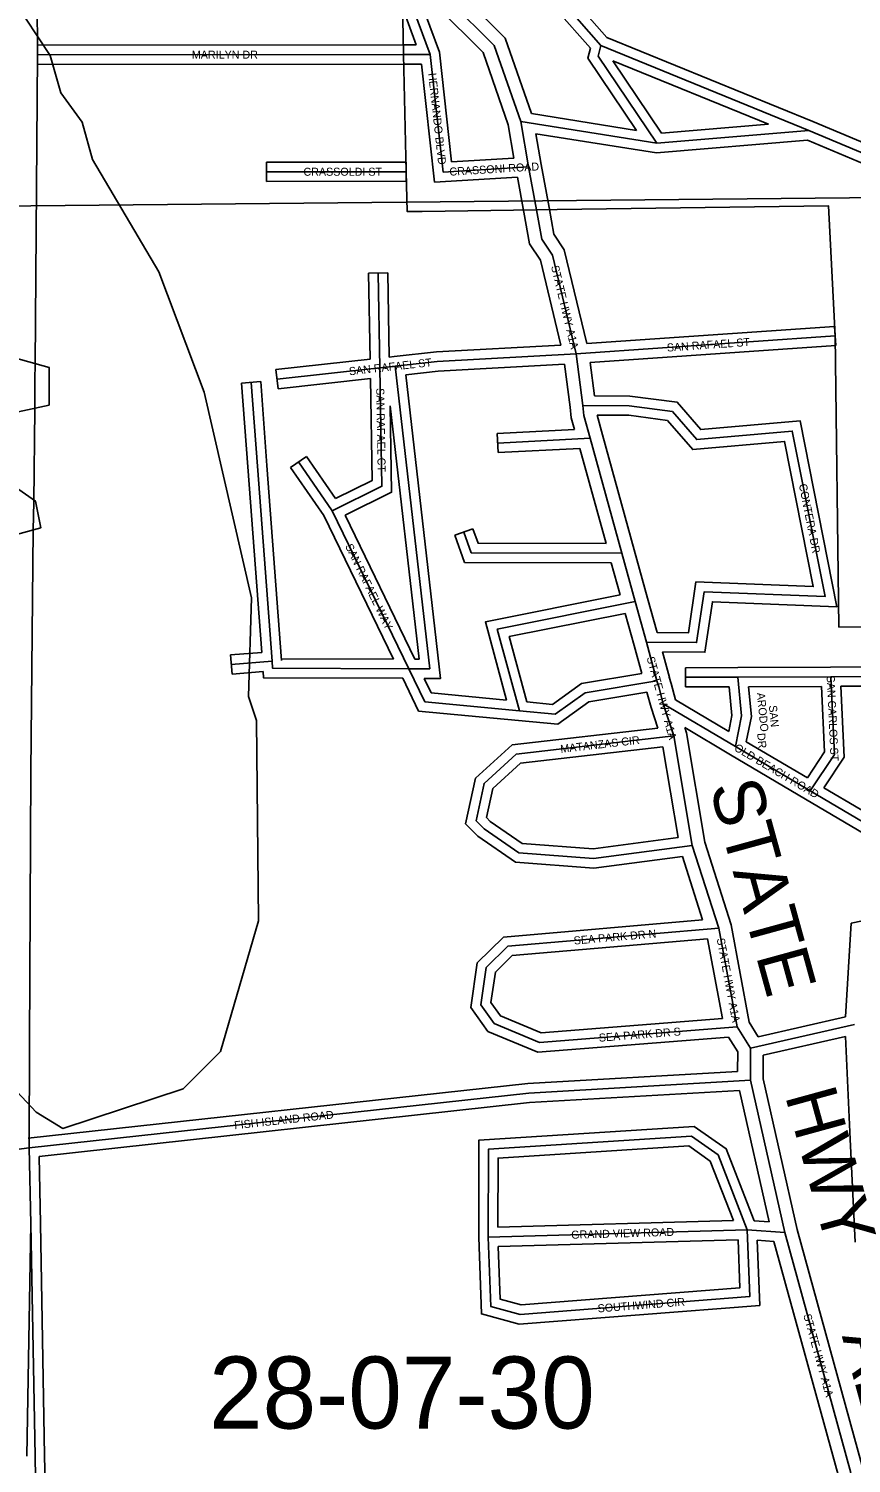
# Model space of a CAD drawing. Extents: x 418523 to 616617, y 1878279 to 2196743.
# Drawn here: x 564365 to 566933, y 2010108 to 2014588 of the extents above; entities that cross this region are included whole.
import ezdxf

# ---------------------------------------------------------------- set-up
doc = ezdxf.new("R2010")
doc.units = 0
for name, color, linetype in [('Level 1', 7, 'Continuous'), ('Level 2', 7, 'Continuous'), ('Level 22', 7, 'Continuous'), ('Level 23', 7, 'Continuous'), ('Level 28', 7, 'Continuous'), ('Level 31', 7, 'Continuous'), ('Level 32', 7, 'Continuous'), ('Level 34', 7, 'Continuous'), ('Level 5', 7, 'Continuous'), ('Level 7', 7, 'Continuous'), ('Level 8', 7, 'Continuous')]:
    doc.layers.add(name, color=color, linetype=linetype)

msp = doc.modelspace()

# ---------------------------------------------------------------- linework, layer by layer
at = {"layer": 'Level 1'}
msp.add_line((562889.28, 2014020.741), (568168.027, 2014072.298), dxfattribs=at)
at = {"layer": 'Level 22'}
for p, q in [((565925.146, 2014156.548), (565900.773, 2014298.436)), ((565949.857, 2014022.661), (565925.146, 2014156.548)), ((566094.474, 2013411.356), (566073.633, 2013572.508)), ((566216.957, 2012949.935), (566117.994, 2013309.11)), ((566258.427, 2012798.915), (566216.957, 2012949.935)), ((566293.299, 2012672.276), (566258.427, 2012798.915)), ((566326.287, 2012551.823), (566293.299, 2012672.276)), ((566331.628, 2012532.536), (566326.287, 2012551.823)), ((566346.079, 2012479.77), (566331.628, 2012532.536)), ((566379.116, 2012379.682), (566346.079, 2012479.77)), ((566436.603, 2012037.702), (566379.116, 2012379.682)), ((566519.019, 2011779.302), (566436.603, 2012037.702)), ((566576.589, 2011470.414), (566519.019, 2011779.302)), ((566618.267, 2011403.763), (566576.589, 2011470.414)), ((566618.023, 2011303.757), (566618.267, 2011403.763)), ((566724.954, 2010828.194), (566618.023, 2011303.757)), ((566931.388, 2010077.461), (566724.954, 2010828.194))]:
    msp.add_line(p, q, dxfattribs=at)
for points in [[(565900.773, 2014298.436), (565818, 2014536.473), (565679.829, 2014673.186)], [(566073.633, 2013572.508), (565999.589, 2013881.438), (565966.431, 2013931.341), (565949.857, 2014022.661)], [(566117.994, 2013309.11), (566098.202, 2013380.799), (566094.474, 2013411.356)]]:
    msp.add_lwpolyline(points, dxfattribs=at)
at = {"layer": 'Level 23'}
for p, q in [((565879.866, 2014183.873), (565861.908, 2014288.412)), ((565964.483, 2014163.807), (565947.874, 2014260.518)), ((565989.194, 2014029.92), (565964.483, 2014163.807)), ((565910.521, 2014015.401), (565890.404, 2014124.399)), ((566054.804, 2013406.225), (566037.44, 2013540.486)), ((566130.939, 2013441.266), (566117.463, 2013545.479)), ((566156.552, 2013319.755), (566139.576, 2013381.244)), ((566255.521, 2012960.56), (566156.558, 2013319.735)), ((566167.156, 2012980.096), (566085.247, 2013277.375)), ((566296.999, 2012809.506), (566255.53, 2012960.526)), ((566211.135, 2012820.076), (566183.685, 2012920.041)), ((566326.594, 2012702.04), (566296.992, 2012809.534)), ((566254.734, 2012661.656), (566227.083, 2012762.073)), ((566278.654, 2012574.316), (566254.719, 2012661.71)), ((566364.868, 2012562.388), (566343.087, 2012641.92)), ((566370.179, 2012543.211), (566364.838, 2012562.498)), ((566384.186, 2012492.068), (566370.209, 2012543.101)), ((566307.772, 2012468.21), (566294.643, 2012516.149)), ((566328.942, 2012404.073), (566307.772, 2012468.21)), ((566418.059, 2012389.321), (566412.746, 2012405.416)), ((566475.579, 2012047.141), (566418.059, 2012389.322)), ((566391.944, 2012062.076), (566344.309, 2012345.45)), ((566557.886, 2011789.081), (566475.579, 2012047.141)), ((566468.814, 2011805.074), (566405.574, 2012003.351)), ((566614.524, 2011485.194), (566557.886, 2011789.081)), ((566530.957, 2011496.933), (566484.498, 2011746.204)), ((566642.717, 2011440.107), (566614.524, 2011485.194)), ((566578.239, 2011392.331), (566549.553, 2011438.204)), ((566578.09, 2011331.512), (566578.239, 2011392.33)), ((566658.035, 2011308.151), (566658.215, 2011382.101)), ((566676.382, 2010861.878), (566584.217, 2011271.764)), ((566763.774, 2010837.889), (566658.035, 2011308.151)), ((566965.801, 2010103.183), (566763.775, 2010837.889)), ((566891.622, 2010071.21), (566691.049, 2010800.625))]:
    msp.add_line(p, q, dxfattribs=at)
for points in [[(565934.432, 2014323.433), (565852.733, 2014558.378), (565732.404, 2014677.438)], [(565861.909, 2014288.412), (565783.267, 2014514.568), (565639.966, 2014656.356)], [(566025.923, 2013599.948), (565962.344, 2013865.213), (565928.547, 2013916.078), (565910.499, 2014015.517)], [(566107.004, 2013604.899), (566036.834, 2013897.663), (566004.315, 2013946.604), (565989.215, 2014029.803)], [(566068.904, 2013336.612), (566058.854, 2013373.012), (566054.804, 2013406.225)]]:
    msp.add_lwpolyline(points, dxfattribs=at)
at = {"layer": 'Level 31'}
for p, q in [((565617.934, 2014507.874), (565556.854, 2014673.491)), ((566800.854, 2014270.771), (566151.431, 2014535.651)), ((565535.525, 2014507.715), (564392.277, 2014506.926)), ((565617.934, 2014507.874), (565535.525, 2014507.715)), ((565658.548, 2014140.478), (565617.934, 2014507.874)), ((566325.642, 2014230.476), (565900.773, 2014298.436)), ((566325.642, 2014230.476), (566800.854, 2014270.771)), ((567158.964, 2014120.071), (566800.854, 2014270.771)), ((565543.497, 2014141.853), (565106.731, 2014141.482)), ((565925.146, 2014156.548), (565658.548, 2014140.478)), ((565455.869, 2013825.322), (565461.157, 2013528.926)), ((566073.633, 2013572.508), (566882.65, 2013628.712)), ((565461.157, 2013528.926), (565139.989, 2013493.722)), ((565461.157, 2013528.926), (565509.349, 2013534.262)), ((565078.775, 2013221.856), (565059.139, 2013483.741)), ((566117.994, 2013309.11), (565829.205, 2013294.184)), ((565312.349, 2013082.722), (565207.178, 2013235.356)), ((565124.491, 2012612.613), (565078.775, 2013221.856)), ((565312.349, 2013082.722), (565551.464, 2012589.371)), ((565124.491, 2012612.613), (564997.361, 2012602.383)), ((565551.464, 2012589.371), (565601.789, 2012485.538)), ((566578.939, 2012563.205), (566415.064, 2012562.516)), ((566868.651, 2012564.315), (566578.939, 2012563.205)), ((567149.488, 2012565.451), (566868.651, 2012564.315)), ((565896.562, 2012457.601), (565601.789, 2012485.538)), ((566571.119, 2012346.483), (566346.079, 2012479.77)), ((566805.024, 2012208.085), (566571.119, 2012346.483)), ((566618.267, 2011403.763), (566943.35, 2011477.883)), ((564371.101, 2010855.837), (564366.621, 2011092.955)), ((566608.325, 2010836.842), (565799.644, 2010814.101)), ((566724.954, 2010828.194), (566608.325, 2010836.842))]:
    msp.add_line(p, q, dxfattribs=at)
for points in [[(566151.431, 2014535.651), (566031.009, 2014672.321), (566023.599, 2014676.651)], [(566325.642, 2014230.476), (566143.109, 2014502.216), (566151.431, 2014535.651)], [(565509.349, 2013534.262), (565640.289, 2013548.848), (566073.633, 2013572.508)], [(565461.157, 2013528.926), (565467.534, 2013159.069), (565312.349, 2013082.722)], [(565509.349, 2013534.262), (565617.003, 2012589.209), (565551.464, 2012589.371)], [(566094.474, 2013411.356), (566239.958, 2013410.998), (566374.305, 2013393.213), (566450.478, 2013305.021), (566748.804, 2013331.566), (566851.193, 2012814.556), (566473.722, 2012829.661), (566450.196, 2012671.163), (566293.299, 2012672.276)], [(566216.957, 2012949.935), (565746.584, 2012951.457), (565723.289, 2013016.246)], [(566258.427, 2012798.915), (565827.774, 2012713.06), (565896.562, 2012457.601)], [(565551.464, 2012589.371), (565126.022, 2012590.79), (565124.491, 2012612.613)], [(566578.939, 2012563.205), (566590.688, 2012442.077), (566571.119, 2012346.483)], [(566868.651, 2012564.315), (566880.104, 2012321.363), (566805.024, 2012208.085)], [(566326.287, 2012551.823), (566102.098, 2012514.553), (566008.427, 2012447.143), (565896.562, 2012457.601)], [(566436.603, 2012037.702), (566127.771, 2011997.003), (565894.52, 2012014.306), (565786.3, 2012089.486), (565761.322, 2012114.641), (565786.649, 2012231.312), (565887.038, 2012322.706), (566379.116, 2012379.682)], [(567236.134, 2011827.376), (567053.49, 2012061.288), (566805.024, 2012208.085)], [(565776.388, 2011539.294), (565793.475, 2011655.986), (565860.52, 2011722.371), (566519.019, 2011779.302)], [(566576.589, 2011470.414), (565959.629, 2011422.108), (565818.085, 2011481.006), (565776.388, 2011539.294)], [(564366.621, 2011092.955), (565925.959, 2011263.999), (566618.023, 2011303.757)], [(562952.402, 2010903.787), (564121.512, 2011060.113), (564366.621, 2011092.955)], [(566608.325, 2010836.842), (566517.288, 2011070.534), (566434.065, 2011129.287), (565800.32, 2011089.025), (565799.644, 2010814.101)], [(564388.429, 2009925.917), (564384.501, 2010130.303), (564371.101, 2010855.837)], [(565799.644, 2010814.101), (565807.352, 2010597.341), (565898.899, 2010572.022), (566616.059, 2010628.447), (566608.325, 2010836.842)]]:
    msp.add_lwpolyline(points, dxfattribs=at)
at = {"layer": 'Level 32'}
for p, q in [((565647.351, 2014514.814), (565587.229, 2014677.83)), ((566169.284, 2014560.77), (566067.283, 2014676.531)), ((565574.924, 2014537.791), (565526.601, 2014668.818)), ((565535.504, 2014537.715), (564392.257, 2014536.926)), ((564392.299, 2014476.926), (564392.257, 2014536.926)), ((565574.924, 2014537.79), (565535.467, 2014537.715)), ((566812.49, 2014298.422), (566169.284, 2014560.769)), ((565685.232, 2014172.141), (565647.351, 2014514.814)), ((565535.546, 2014477.714), (564392.299, 2014476.926)), ((565591.074, 2014477.821), (565535.584, 2014477.714)), ((565631.865, 2014108.813), (565591.073, 2014477.821)), ((566673.975, 2014290.121), (566188.789, 2014488.013)), ((566340.702, 2014261.861), (566188.789, 2014488.013)), ((566262.286, 2014270.991), (565934.432, 2014323.433)), ((566340.701, 2014261.861), (566673.975, 2014290.121)), ((567172.013, 2014147.128), (566812.49, 2014298.422)), ((566324.524, 2014200.272), (565947.874, 2014260.518)), ((566324.524, 2014200.272), (566796.029, 2014240.252)), ((567145.916, 2014093.011), (566796.029, 2014240.252)), ((565879.866, 2014183.872), (565685.232, 2014172.141)), ((565543.471, 2014171.853), (565106.706, 2014171.482)), ((565106.758, 2014111.481), (565106.706, 2014171.482)), ((565543.523, 2014111.852), (565543.471, 2014171.853)), ((565543.523, 2014111.852), (565106.758, 2014111.481)), ((565890.404, 2014124.398), (565631.865, 2014108.813)), ((565485.865, 2013825.857), (565425.873, 2013824.787)), ((565425.873, 2013824.787), (565430.674, 2013555.764)), ((565485.865, 2013825.857), (565490.567, 2013562.366)), ((566107.004, 2013604.899), (566880.572, 2013658.64)), ((566880.572, 2013658.64), (566884.73, 2013598.783)), ((566117.463, 2013545.479), (566884.73, 2013598.783)), ((565430.674, 2013555.764), (565136.72, 2013523.543)), ((565490.566, 2013562.366), (565506.048, 2013564.081)), ((565143.259, 2013463.9), (565136.72, 2013523.543)), ((565029.223, 2013481.497), (565089.057, 2013485.984)), ((565048.859, 2013219.613), (565029.223, 2013481.497)), ((565108.693, 2013224.1), (565089.057, 2013485.984)), ((565431.729, 2013495.52), (565143.259, 2013463.9)), ((566068.904, 2013336.613), (565827.657, 2013324.145)), ((565830.754, 2013264.222), (565827.657, 2013324.145)), ((565182.474, 2013218.335), (565231.883, 2013252.378)), ((565322.354, 2013121.078), (565231.883, 2013252.378)), ((566085.246, 2013277.375), (565830.754, 2013264.222)), ((565092.343, 2012640.123), (565048.859, 2013219.611)), ((565154.409, 2012614.858), (565108.693, 2013224.101)), ((565286.349, 2013067.581), (565182.474, 2013218.335)), ((565286.349, 2013067.581), (565503.507, 2012619.532)), ((565352.354, 2013068.967), (565570.284, 2012619.325)), ((565695.057, 2013006.095), (565751.519, 2013026.396)), ((565092.343, 2012640.123), (564994.954, 2012632.287)), ((564999.769, 2012572.478), (564994.954, 2012632.287)), ((565503.507, 2012619.532), (565153.999, 2012620.697)), ((565096.685, 2012580.277), (564999.769, 2012572.478)), ((566578.812, 2012593.205), (566414.937, 2012592.516)), ((566415.191, 2012532.515), (566414.937, 2012592.516)), ((566868.536, 2012594.315), (566578.824, 2012593.205)), ((567149.366, 2012595.45), (566868.529, 2012594.315)), ((565532.635, 2012559.434), (565582.154, 2012457.264)), ((565599.399, 2012559.252), (565621.424, 2012513.812)), ((566551.719, 2012533.089), (566415.191, 2012532.515)), ((566840.038, 2012534.204), (566611.978, 2012533.33)), ((567120.232, 2012535.33), (566900.094, 2012534.441)), ((565856.353, 2012491.546), (565621.424, 2012513.812)), ((566550.174, 2012393.756), (566384.186, 2012492.067)), ((565893.731, 2012427.733), (565582.154, 2012457.264)), ((566555.831, 2012320.67), (566412.746, 2012405.416)), ((566795.766, 2012248.421), (566604.799, 2012361.414)), ((566789.747, 2012182.265), (566555.843, 2012320.663)), ((566932.284, 2011794.143), (567182.878, 2011846.833)), ((566914.753, 2011502.132), (566932.284, 2011794.143)), ((566642.717, 2011440.107), (566914.753, 2011502.132)), ((566658.215, 2011382.1), (566915.049, 2011440.658)), ((566915.048, 2011440.658), (566929.949, 2011120.064)), ((566929.949, 2011120.085), (566944.699, 2010797.847)), ((564401.096, 2010856.403), (564397.135, 2011066.12)), ((566564.914, 2010865.633), (565829.721, 2010844.957)), ((566676.381, 2010861.878), (566629.413, 2010865.361)), ((566579.449, 2010806.017), (565830.699, 2010784.961)), ((566691.05, 2010800.625), (566639.55, 2010804.443))]:
    msp.add_line(p, q, dxfattribs=at)
for points in [[(566118.519, 2014527.625), (566011.696, 2014648.859), (565963.864, 2014676.812)], [(566262.286, 2014270.991), (566110.779, 2014496.541), (566118.519, 2014527.625)], [(565506.028, 2013564.079), (565637.809, 2013578.758), (566025.923, 2013599.947)], [(565542.561, 2013507.775), (565650.624, 2012559.125), (565599.399, 2012559.252)], [(565542.562, 2013507.776), (565642.77, 2013518.938), (566037.44, 2013540.486)], [(565431.729, 2013495.52), (565437.209, 2013177.585), (565322.354, 2013121.077)], [(566130.939, 2013441.266), (566241.971, 2013440.994), (566389.553, 2013421.457), (566463.133, 2013336.266), (566772.996, 2013363.837), (566888.014, 2012783.057), (566499.442, 2012798.607), (566476.045, 2012640.979), (566343.087, 2012641.92)], [(565493.196, 2013411.009), (565497.859, 2013140.553), (565352.354, 2013068.968)], [(565493.196, 2013411.009), (565583.381, 2012619.292), (565570.284, 2012619.325)], [(566139.576, 2013381.244), (566237.944, 2013381.002), (566359.058, 2013364.969), (566437.823, 2013273.776), (566724.611, 2013299.293), (566814.371, 2012846.054), (566448.002, 2012860.715), (566424.346, 2012701.348), (566326.594, 2012702.041)], [(566167.155, 2012980.096), (565767.703, 2012981.39), (565751.519, 2013026.396)], [(566183.685, 2012920.041), (565725.466, 2012921.524), (565695.057, 2013006.095)], [(566211.134, 2012820.077), (565790.471, 2012736.214), (565856.353, 2012491.546)], [(566227.083, 2012762.073), (565865.079, 2012689.906), (565920.112, 2012485.53)], [(565532.635, 2012559.434), (565098.045, 2012560.881), (565096.685, 2012580.277)], [(566278.654, 2012574.316), (566090.263, 2012542.997), (566000.027, 2012478.059), (565920.111, 2012485.53)], [(566551.719, 2012533.089), (566560.391, 2012443.673), (566550.174, 2012393.756)], [(566611.978, 2012533.33), (566620.984, 2012440.481), (566604.799, 2012361.413)], [(566840.037, 2012534.204), (566849.674, 2012329.756), (566795.767, 2012248.421)], [(566900.094, 2012534.441), (566910.534, 2012312.971), (566847.485, 2012217.843)], [(566294.643, 2012516.149), (566113.933, 2012486.108), (566016.827, 2012416.226), (565893.769, 2012427.73)], [(566405.574, 2012003.351), (566128.631, 2011966.856), (565884.131, 2011984.993), (565766.939, 2012066.407), (565728.545, 2012105.071), (565759.365, 2012247.044), (565873.987, 2012351.396), (566328.942, 2012404.073)], [(566391.944, 2012062.076), (566126.911, 2012027.15), (565904.909, 2012043.618), (565805.662, 2012112.566), (565794.099, 2012124.21), (565813.934, 2012215.581), (565900.089, 2012294.017), (566344.309, 2012345.45)], [(567252.321, 2011855.392), (567073.641, 2012084.228), (566847.485, 2012217.843)], [(567182.878, 2011846.833), (567033.339, 2012038.348), (566789.764, 2012182.256)], [(565744.952, 2011531.675), (565765.244, 2011670.252), (565847.124, 2011751.326), (566468.814, 2011805.074)], [(565807.825, 2011546.912), (565821.707, 2011641.721), (565873.917, 2011693.416), (566484.498, 2011746.204)], [(566530.957, 2011496.933), (565964.488, 2011452.581), (565837.509, 2011505.418), (565807.825, 2011546.913)], [(566549.553, 2011438.204), (565954.772, 2011391.635), (565798.662, 2011456.593), (565744.952, 2011531.674)], [(564362.994, 2011122.736), (565923.46, 2011293.906), (566578.09, 2011331.512)], [(564397.135, 2011066.12), (565928.457, 2011234.092), (566584.217, 2011271.765)], [(566629.413, 2010865.361), (566541.965, 2011089.836), (566442.724, 2011159.898), (565770.389, 2011117.185), (565769.643, 2010813.603)], [(566564.914, 2010865.633), (566492.61, 2011051.233), (566425.408, 2011098.676), (565830.252, 2011060.866), (565829.721, 2010844.958)], [(564417.745, 2009961.841), (564414.497, 2010130.869), (564401.096, 2010856.391)], [(565769.642, 2010813.603), (565778.151, 2010574.29), (565895.99, 2010541.7), (566647.106, 2010600.796), (566639.55, 2010804.443)], [(565830.7, 2010784.961), (565836.552, 2010620.391), (565901.807, 2010602.345), (566585.012, 2010656.097), (566579.449, 2010806.016)]]:
    msp.add_lwpolyline(points, dxfattribs=at)
at = {"layer": 'Level 5'}
for points in [[(564061.689, 2013430.948), (564278.275, 2013380.24), (564428.419, 2013413.092), (564428.816, 2013529.805), (564095.657, 2013622.583)], [(564052.404, 2013139.201), (564285.362, 2012996.731), (564402.174, 2013029.723), (564385.763, 2013113.115), (564252.678, 2013205.246), (564069.373, 2013230.874)]]:
    msp.add_lwpolyline(points, dxfattribs=at)
at = {"layer": 'Level 7'}
msp.add_lwpolyline([(564315.793, 2014680.58), (564431.949, 2014505.157), (564464.932, 2014388.345), (564531.295, 2014296.424), (564564.288, 2014179.611), (564771.549, 2013828.796), (564912.059, 2013453.209), (565060.064, 2012810.816), (565050.709, 2012502.399), (565075.491, 2012427.307), (565081.803, 2011802.053), (564963.757, 2011393.963), (564846.686, 2011277.619), (564471.129, 2011153.781), (564387.927, 2011204.091), (563432.546, 2012224.203)], dxfattribs=at)
at = {"layer": 'Level 8'}
for points in [[(564391.586, 2014681.064), (564392.248, 2014506.666), (564385.265, 2013539.645), (564384.266, 2013493.643), (564384.268, 2013399.641), (564380.273, 2013110.635), (564378.274, 2013021.633), (564371.287, 2012267.616), (564367.302, 2011418.596), (564366.308, 2011092.588), (564371.313, 2010855.583), (564359.325, 2010129.566)], [(568247.423, 2009781.606), (568240.417, 2010115.614), (568235.393, 2011474.645), (568236.387, 2011794.651), (568236.386, 2011832.652), (568201.369, 2012730.672), (566894.339, 2012719.656), (566882.322, 2013628.677), (566862.314, 2014034.686), (566014.294, 2014023.676), (565950.294, 2014022.675), (565593.285, 2014017.67), (565546.284, 2014017.67), (565543.282, 2014141.672), (565535.275, 2014507.681), (565532.272, 2014673.684)]]:
    msp.add_lwpolyline(points, dxfattribs=at)

# ---------------------------------------------------------------- texts
at = {"layer": 'Level 2'}
msp.add_text('28-07-30', height=225, dxfattribs=at).set_placement((564927.637, 2010216.086))
at = {"layer": 'Level 28'}
for s, p in [('STATE', (566489.537, 2012220.954)), ('HWY', (566725.3, 2011256.837)), ('A1A', (566903.081, 2010505.01))]:
    msp.add_text(s, height=160, rotation=285.374, dxfattribs=at).set_placement(p)
at = {"layer": 'Level 34'}
for s, height, rotation, p in [('MARILYN DR', 25, 0.038814, (564874.145, 2014494.761)), ('HERNANDO BLVD', 25, 276.307222, (565611.906, 2014448.651)), ('CRASSOLDI ST', 25, 0.047956, (565222.604, 2014129.083)), ('CRASSONI ROAD', 25, 3.448847, (565678.947, 2014129.187)), ('STATE HWY A1A', 24.99916, 283.477267, (565995.26, 2013845.876)), ('SAN RAFAEL ST', 24.99916, 3.973344, (566357.892, 2013579.729)), ('SAN RAFAEL ST', 25, 6.317133, (565365.949, 2013505.811)), ('SAN RAFAEL CT', 25, 270.986603, (565449.748, 2013465.656)), ('CONTERA DR', 25, 281.200872, (566769.105, 2013164.712)), ('SAN RAFAEL WAY', 25, 295.857269, (565351.964, 2012972.331)), ('STATE HWY A1A', 25, 285.315442, (566293.708, 2012623.679)), ('SAN CARLOS ST', 25, 272.698147, (566855.998, 2012567.309)), ('ARODO', 25, 275.5393, (566638.142, 2012513.549)), ('SAN', 25, 275.5393, (566675.603, 2012474.228)), ('DR', 25, 275.5393, (566638.944, 2012387.428)), ('MATANZAS CIR', 24.99916, 6.603925, (566026.114, 2012326.228)), ('OLD BEACH ROAD', 25, 329.386906, (566565.012, 2012335.575)), ('SEA PARK DR N', 25, 4.940589, (566067.526, 2011727.723)), ('STATE HWY A1A', 25, 280.556481, (566512.564, 2011745.724)), ('SEA PARK DR S', 25, 4.476336, (566145.683, 2011424.14)), ('FISH ISLAND ROAD', 25, 6.259083, (565007.704, 2011150.702)), ('GRAND VIEW ROAD', 25, 1.6102, (566058.881, 2010808.888)), ('SOUTHWIND CIR', 24.99916, 4.497972, (566142.129, 2010578.623)), ('STATE HWY A1A', 25, 285.373989, (566782.905, 2010570.306))]:
    msp.add_text(s, height=height, rotation=rotation, dxfattribs=at).set_placement(p)

doc.saveas('drawing.dxf')
